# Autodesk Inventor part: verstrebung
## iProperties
Created: 2005-05
Part Number: verstrebung
Document SubType Name: Sheet Metal
Designer: Mario Wipf
Manufacturer: Standard
Standards Organization: Custom
Author: Mario Wipf
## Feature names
1. Eckenfase1
2. Grobblech1
